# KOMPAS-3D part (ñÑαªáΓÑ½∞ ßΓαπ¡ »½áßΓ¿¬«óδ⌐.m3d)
File: created 25.10.2015 21:59:19, last saved 10.03.2016 22:26:27.
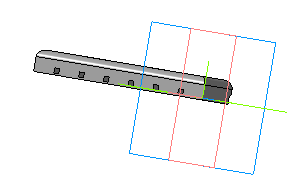
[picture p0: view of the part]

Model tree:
1. Эскиз:1
2. Операция выдавливания:1
     Расстояние 1 = 30
3. Эскиз:2
4. Операция выдавливания:2
     Расстояние 1 = 20; Расстояние 2 = 30
5. Скругление:1
     Радиус = 3
6. Эскиз:3
7. Вырезать элемент выдавливания:1
     Расстояние 1 = 20
8. Эскиз:4
9. Вырезать элемент выдавливания:2
     Расстояние 1 = 4; Угол 1 = 32
10. Эскиз:5
11. Вырезать элемент выдавливания:3
     Расстояние 2 = 20; Расстояние 1 = 94
12. Эскиз:6
13. Вырезать элемент выдавливания:4
     Расстояние 1 = 40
